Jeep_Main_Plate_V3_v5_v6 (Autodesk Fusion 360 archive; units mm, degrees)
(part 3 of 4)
sketch "Sketch11" plane through (0, 0, 2) normal (0, 0, 1) x axis (-1, 0, 0)
  line L1 (0.6323, -2.2) -> (-11.4211, -2.2)
  line L2 (17.4051, 39.633) -> (0.6323, -2.2)
  line L3 (7.0123, 43.8) -> (17.4051, 39.633)
  line L4 (3.9887, 36.2589) -> (7.0123, 43.8)
  line L5 (2.418, 37.7236) -> (3.9887, 36.2589)
  line L6 (-10.5895, 5.2816) -> (2.418, 37.7236)
  line L7 (-8.4377, 5.259) -> (-10.5895, 5.2816)
  line L8 (-11.4211, -2.2) -> (-8.4377, 5.259)
  line L9 (11.4644, 39.8602) -> (12.2087, 41.7165)
  line L10 (4.9672, 42.4652) -> (11.4644, 39.8602)
  line L11 (19.452, 36.6576) -> (10.1703, 40.379)
  line L12 (14.2412, 37.1163) -> (16.0976, 36.372)
  line L13 (14.8112, 38.5183) -> (14.2412, 37.1163)
  line L14 (-4.3662, -9.2924) -> (14.2412, 37.1163)
  point P10 (12.2087, 41.7165)
  point P13 (10.1703, 40.379)
  point P15 (16.0976, 36.372)
  point P17 (14.8112, 38.5183)
  point P11 (11.4644, 39.8602)
  point P12 (4.9672, 42.4652)
  point P14 (19.452, 36.6576)
  point P16 (14.2412, 37.1163)
  point P18 (-4.3662, -9.2924)
  midpoint L3 P10
  coincident L10 P13
  coincident L2 P15
  midpoint L11 P17
  dimension "d95" distance P10 P11 = 2
  dimension "d96" distance P11 P12 = 7
  dimension "d97" distance P13 P14 = 10
  dimension "d98" distance P15 P16 = 2
  dimension "d99" distance P16 P18 = 50
extrude "Extrude11" add sketch "Sketch11" profile of L2 L3 L4 L9 L10 L11 along normal blind 13
sketch "Sketch12" plane through (0, 0, 2) normal (0, 0, 1) x axis (-1, 0, 0)
  line L1 (6.268, 41.9437) -> (16.6608, 37.7767)
  line L2 (3.9887, 36.2589) -> (6.268, 41.9437)
  line L3 (2.418, 37.7236) -> (3.9887, 36.2589)
  line L4 (-10.5895, 5.2816) -> (2.418, 37.7236)
  line L5 (-8.4377, 5.259) -> (-10.5895, 5.2816)
  line L6 (-11.4211, -2.2) -> (-8.4377, 5.259)
  line L7 (0.6323, -2.2) -> (-11.4211, -2.2)
  line L8 (16.6608, 37.7767) -> (0.6323, -2.2)
  line L9 (14.8044, 38.521) -> (16.6608, 37.7767)
  line L10 (-0.0815, 1.3941) -> (14.8044, 38.521)
  line L11 (4, 1.3941) -> (-0.0815, 1.3941)
  point P2 (16.6608, 37.7767)
  point P10 (16.6608, 37.7767)
  point P11 (14.8044, 38.521)
  point P12 (-0.0815, 1.3941)
  point P13 (4, 1.3941)
  coincident P2 P10
  horizontal L11
  dimension "d102" distance P10 P11 = 2
  dimension "d103" distance P11 P12 = 40
  dimension "d104" distance P12 P13 = 4.0815
extrude "Extrude12" add of existing geometry blind 2
sketch "Sketch13" plane through (0, 0, 2) normal (0, 0, 1) x axis (-1, 0, 0)
  line L1 (6.268, 41.9437) -> (18.5171, 37.0324)
  line L2 (3.9887, 36.2589) -> (6.268, 41.9437)
  line L3 (2.418, 37.7236) -> (3.9887, 36.2589)
  line L4 (-10.5895, 5.2816) -> (2.418, 37.7236)
  line L5 (-8.4377, 5.259) -> (-10.5895, 5.2816)
  line L6 (-11.4211, -2.2) -> (-8.4377, 5.259)
  line L7 (0.6323, -2.2) -> (-11.4211, -2.2)
  line L8 (2.4886, -2.9443) -> (0.6323, -2.2)
  line L9 (18.5171, 37.0324) -> (2.4886, -2.9443)
  line L10 (16.6608, 37.7767) -> (18.5171, 37.0324)
  line L11 (1.7749, 0.6498) -> (16.6608, 37.7767)
  line L12 (7.7749, 0.6498) -> (1.7749, 0.6498)
  point P2 (18.5171, 37.0324)
  point P11 (18.5171, 37.0324)
  point P12 (16.6608, 37.7767)
  point P13 (1.7749, 0.6498)
  point P14 (7.7749, 0.6498)
  coincident P2 P11
  dimension "d107" distance P11 P12 = 2
  dimension "d108" distance P12 P13 = 40
  dimension "d109" distance P13 P14 = 6
extrude "Extrude13" add sketch "Sketch13" profile of L1 L9 L10 L11 L12 along normal blind 10
sketch "Sketch14" plane through (-3.161, 1.2674, 0) normal (-0.9282, 0.3721, 0) x axis (-0.3721, -0.9282, 0)
  line L1 (43.2636, 15) -> (43.2636, 0)
  line L2 (41.2636, 15) -> (43.2636, 15)
  line L3 (41.2636, 12) -> (41.2636, 15)
  line L4 (2.0655, 12) -> (41.2636, 12)
  line L5 (2.0655, 2) -> (2.0655, 12)
  line L6 (-1.8067, 2) -> (2.0655, 2)
  line L7 (-1.8067, 0) -> (-1.8067, 2)
  line L8 (43.2636, 0) -> (-1.8067, 0)
sketch "Sketch15" plane through (0, 0, 2) normal (0, 0, 1) x axis (-1, 0, 0)
  line L1 (1.7749, 0.6498) -> (3.9296, 0.6498)
  line L2 (16.6608, 37.7767) -> (1.7749, 0.6498)
  line L3 (6.268, 41.9437) -> (16.6608, 37.7767)
  line L4 (3.9887, 36.2589) -> (6.268, 41.9437)
  line L5 (2.418, 37.7236) -> (3.9887, 36.2589)
  line L6 (-10.5895, 5.2816) -> (2.418, 37.7236)
  line L7 (-8.4377, 5.259) -> (-10.5895, 5.2816)
  line L8 (-11.4211, -2.2) -> (-8.4377, 5.259)
  line L9 (0.6323, -2.2) -> (-11.4211, -2.2)
  line L10 (2.4886, -2.9443) -> (0.6323, -2.2)
  line L11 (3.9296, 0.6498) -> (2.4886, -2.9443)
  arc A1 centre (-11.4211, 40.5698) radius 42.7698 clockwise from (3.9296, 0.6498) to (-11.4211, -2.2)
  point P10 (-11.4211, -2.2)
  point P14 (-11.4211, -2.2)
  point P2 (3.9296, 0.6498)
  point P13 (3.9296, 0.6498)
  tangent L9 A1
  coincident P10 P14
  coincident P2 P13
extrude "Extrude14" cut sketch "Sketch15" profile of L9 L10 L11 A1 against normal blind 4
extrude "Extrude15" add of existing geometry blind 0.5
sketch "Sketch16" plane through (0, 0, 15) normal (0, 0, 1) x axis (-1, 0, 0)
  line L1 (-8.4377, 5.259) -> (-11.4211, -2.2)
  line L2 (-10.5895, 5.2816) -> (-8.4377, 5.259)
  line L3 (2.418, 37.7236) -> (-10.5895, 5.2816)
  line L4 (3.9887, 36.2589) -> (2.418, 37.7236)
  line L5 (6.268, 41.9437) -> (3.9887, 36.2589)
  line L6 (18.9812, 36.8463) -> (6.268, 41.9437)
  line L7 (19.7255, 38.7027) -> (18.9812, 36.8463)
  line L8 (7.0123, 43.8) -> (19.7255, 38.7027)
  line L9 (-5, 43.8) -> (7.0123, 43.8)
  line L10 (-5, 42.6) -> (-5, 43.8)
  line L11 (0, 42.6) -> (-5, 42.6)
  line L12 (-57.3, 0) -> (-43.8, 0)
  line L13 (-60.8, 11) -> (-60.8, 3.5)
  line L14 (-62, 11) -> (-60.8, 11)
  line L15 (-62, 0.8) -> (-62, 11)
  line L16 (-11.4211, -2.2) -> (-59, -2.2)
  arc A1 centre (-49.0833, 49.2491) radius 49.5316 clockwise from (0, 42.6) to (-43.8, 0)
  arc A2 centre (-54.6577, 6.1423) radius 6.6865 clockwise from (-57.3, 0) to (-60.8, 3.5)
  arc A3 centre (-59, 0.8) radius 3 clockwise from (-59, -2.2) to (-62, 0.8)
extrude "Extrude16" cut of existing geometry blind -0.9
sketch "Sketch17" plane through (0, 0, 15) normal (0, 0, 1) x axis (-1, 0, 0)
  line L1 (-8.4377, 5.259) -> (-11.4211, -2.2)
  line L2 (-10.5895, 5.2816) -> (-8.4377, 5.259)
  line L3 (2.418, 37.7236) -> (-10.5895, 5.2816)
  line L4 (3.9887, 36.2589) -> (2.418, 37.7236)
  line L5 (6.268, 41.9437) -> (3.9887, 36.2589)
  line L6 (18.9812, 36.8463) -> (6.268, 41.9437)
  line L7 (19.7255, 38.7027) -> (18.9812, 36.8463)
  line L8 (7.0123, 43.8) -> (19.7255, 38.7027)
  line L9 (-5, 43.8) -> (7.0123, 43.8)
  line L10 (-5, 42.6) -> (-5, 43.8)
  line L11 (0, 42.6) -> (-5, 42.6)
  line L12 (-57.3, 0) -> (-43.8, 0)
  line L13 (-60.8, 11) -> (-60.8, 3.5)
  line L14 (-62, 11) -> (-60.8, 11)
  line L15 (-62, 0.8) -> (-62, 11)
  line L16 (-11.4211, -2.2) -> (-59, -2.2)
  arc A1 centre (-49.0833, 49.2491) radius 49.5316 clockwise from (0, 42.6) to (-43.8, 0)
  arc A2 centre (-54.6577, 6.1423) radius 6.6865 clockwise from (-57.3, 0) to (-60.8, 3.5)
  arc A3 centre (-59, 0.8) radius 3 clockwise from (-59, -2.2) to (-62, 0.8)
sketch "Sketch18" plane through (0, 0, 12) normal (0, 0, 1) x axis (-1, 0, 0)
  line L1 (2.7445, 0.6498) -> (17.4961, 37.4418)
  line L2 (3.9296, 0.6498) -> (2.7445, 0.6498)
  line L3 (4.3937, 0.4637) -> (3.9296, 0.6498)
  line L4 (18.9812, 36.8463) -> (4.3937, 0.4637)
  line L5 (17.4961, 37.4418) -> (18.9812, 36.8463)
  line L6 (10.0532, 18.8783) -> (17.4961, 37.4418)
  line L7 (15.3685, 18.8783) -> (10.0532, 18.8783)
  point P2 (17.4961, 37.4418)
  point P7 (17.4961, 37.4418)
  point P8 (10.0532, 18.8783)
  coincident P2 P7
  horizontal L7
  dimension "d118" distance P7 P8 = 20
extrude "Extrude17" cut sketch "Sketch18" profile of L1 L2 L3 L4 L7 against normal blind 10
sketch "Sketch19" plane through (0, 0, 2) normal (0, 0, 1) x axis (-1, 0, 0)
  line L1 (6.268, 41.9437) -> (17.4961, 37.4418)
  line L2 (3.9887, 36.2589) -> (6.268, 41.9437)
  line L3 (2.418, 37.7236) -> (3.9887, 36.2589)
  line L4 (-10.5895, 5.2816) -> (2.418, 37.7236)
  line L5 (-8.4377, 5.259) -> (-10.5895, 5.2816)
  line L6 (-11.4211, -2.2) -> (-8.4377, 5.259)
  line L7 (4.3937, 0.4637) -> (3.9296, 0.6498)
  line L8 (11.777, 18.8783) -> (4.3937, 0.4637)
  line L9 (10.0532, 18.8783) -> (11.777, 18.8783)
  line L10 (17.4961, 37.4418) -> (10.0532, 18.8783)
  arc A1 centre (-11.4211, 40.5698) radius 42.7698 clockwise from (3.9296, 0.6498) to (-11.4211, -2.2)
  arc A2 centre (-10.5418, 20.0938) radius 22.3111 clockwise from (6.4823, 5.6727) to (-11.4211, -2.2)
  point P15 (6.4823, 5.6727)
  point P8 (-11.4211, -2.2)
  point P14 (-11.4211, -2.2)
  coincident L8 P15
  coincident P8 P14
extrude "Extrude18" cut sketch "Sketch19" profile of A1 L7 L8 A2 against normal blind 10
fillet "Fillet3" radius 3
fillet "Fillet4" radius 4
fillet "Fillet5" radius 2
fillet "Fillet6" radius 7.25
sketch "Sketch20" plane through (0, 0, 2) normal (0, 0, 1) x axis (-1, 0, 0)
  line L1 (11.777, 18.8783) -> (6.4823, 5.6727)
  line L2 (10.0532, 18.8783) -> (11.777, 18.8783)
  line L3 (17.4961, 37.4418) -> (10.0532, 18.8783)
  line L4 (6.268, 41.9437) -> (17.4961, 37.4418)
  line L5 (3.9887, 36.2589) -> (6.268, 41.9437)
  line L6 (2.418, 37.7236) -> (3.9887, 36.2589)
  line L7 (-10.5895, 5.2816) -> (2.418, 37.7236)
  line L8 (-8.4377, 5.259) -> (-10.5895, 5.2816)
  line L9 (-10.4154, 0.3145) -> (-8.4377, 5.259)
  line L10 (-11.4211, -2.2) -> (-14.1293, -2.2)
  line L11 (3.9887, 36.2589) -> (-8.4377, 5.259)
  arc A1 centre (-10.5418, 20.0938) radius 22.3111 clockwise from (6.4823, 5.6727) to (-7.7545, -2.0425)
  arc A2 centre (-14.1293, 1.8) radius 4 clockwise from (-10.4154, 0.3145) to (-14.1293, -2.2)
  arc A3 centre (-11.4211, 40.5698) radius 42.7698 clockwise from (-7.7545, -2.0425) to (-11.4211, -2.2)
  point P12 (-8.4377, 5.259)
  point P18 (-8.4377, 5.259)
  point P9 (3.9887, 36.2589)
  point P19 (3.9887, 36.2589)
  coincident P12 P18
  coincident P9 P19
extrude "Extrude19" new body sketch "Sketch20" profile of L6 L7 L8 L11 along normal blind 13
sketch "Sketch21" plane through (0, 0, 15) normal (0, 0, 1) x axis (-1, 0, 0)
  line L1 (3.9887, 36.2589) -> (-8.4377, 5.259)
  line L2 (2.418, 37.7236) -> (3.9887, 36.2589)
  line L3 (-10.5895, 5.2816) -> (2.418, 37.7236)
  line L4 (-8.4377, 5.259) -> (-10.5895, 5.2816)
move "Move2"
sketch "Sketch22" plane through (0, 0, 34) normal (0, 0, 1) x axis (-1, 0, 0)
  line L1 (3.9887, 36.2589) -> (-8.4377, 5.259)
  line L2 (2.418, 37.7236) -> (3.9887, 36.2589)
  line L3 (-10.5895, 5.2816) -> (2.418, 37.7236)
  line L4 (-8.4377, 5.259) -> (-10.5895, 5.2816)
sketch "Sketch23" plane through (0, 0, 34) normal (0, 0, 1) x axis (-1, 0, 0)
  line L1 (3.9887, 36.2589) -> (-8.4377, 5.259)
  line L2 (2.418, 37.7236) -> (3.9887, 36.2589)
  line L3 (-10.5895, 5.2816) -> (2.418, 37.7236)
  line L4 (-8.4377, 5.259) -> (-10.5895, 5.2816)
  line L5 (7.0123, 49.1821) -> (1.6236, 35.7422)
  line L6 (18.9812, 36.8463) -> (6.268, 41.9437)
  line L7 (17.4961, 37.4418) -> (6.268, 41.9437)
  line L8 (4.4089, 42.689) -> (7.6114, 41.405)
  line L9 (6.268, 41.9437) -> (3.9887, 36.2589)
  line L10 (-15.0954, -5.9565) -> (-9.5797, 7.8002)
  line L11 (-12.7752, -5.5616) -> (-7.2156, 8.308)
  line L12 (-6.614, -0.9257) -> (-12.183, 1.3072)
  point P6 (1.6236, 35.7422)
  point P12 (7.6114, 41.405)
  point P13 (4.4089, 42.689)
  point P3 (3.9887, 36.2589)
  point P14 (3.9887, 36.2589)
  point P8 (6.268, 41.9437)
  point P15 (6.268, 41.9437)
  point P16 (-9.5797, 7.8002)
  point P18 (-7.2156, 8.308)
  point P20 (-12.183, 1.3072)
  point P21 (-6.614, -0.9257)
  coincident L3 P6
  parallel L3 L5
  coincident L6 P12
  coincident L5 P13
  perpendicular L5 L8
  coincident P3 P14
  coincident P8 P15
  coincident L3 P16
  parallel L3 L10
  coincident L1 P18
  parallel L1 L11
  coincident L10 P20
  dimension "d129" distance P20 P21 = 6
extrude "Extrude20" add sketch "Sketch23" profile of L1 L2 L3 L4 L5 L8 L9 L10 L11 L12 along normal blind 40
sketch "Sketch24" plane through (0, 0, 74) normal (0, 0, 1) x axis (-1, 0, 0)
  line L1 (-12.183, 1.3072) -> (4.4089, 42.689)
  line L2 (-10.3211, 0.5606) -> (-12.183, 1.3072)
  line L3 (3.9887, 36.2589) -> (-10.3211, 0.5606)
  line L4 (6.268, 41.9437) -> (3.9887, 36.2589)
  line L5 (4.4089, 42.689) -> (6.268, 41.9437)
remove_body "RemoveBody1"
sketch "Sketch25" plane through (0, 0, 2) normal (0, 0, 1) x axis (-1, 0, 0)
  line L1 (11.777, 18.8783) -> (6.4823, 5.6727)
  line L2 (10.0532, 18.8783) -> (11.777, 18.8783)
  line L3 (17.4961, 37.4418) -> (10.0532, 18.8783)
  line L4 (6.268, 41.9437) -> (17.4961, 37.4418)
  line L5 (3.9887, 36.2589) -> (6.268, 41.9437)
  line L6 (2.418, 37.7236) -> (3.9887, 36.2589)
  line L7 (-10.5895, 5.2816) -> (2.418, 37.7236)
  line L8 (-8.4377, 5.259) -> (-10.5895, 5.2816)
  line L9 (-10.4154, 0.3145) -> (-8.4377, 5.259)
  line L10 (-11.4211, -2.2) -> (-14.1293, -2.2)
  line L11 (-8.4377, 5.259) -> (-11.4211, -2.2)
  line L12 (8.3111, 47.134) -> (-9.9294, 1.5295)
  line L13 (3.9887, 36.2589) -> (-10.3211, 0.5606)
  line L14 (3.9887, 36.2589) -> (-8.4377, 5.259)
  line L15 (-11.7486, -3.0312) -> (-6.1781, 10.8961)
  line L16 (-25.6775, -38.0332) -> (7.6802, 45.5567)
  arc A1 centre (-10.5418, 20.0938) radius 22.3111 clockwise from (6.4823, 5.6727) to (-7.7545, -2.0425)
  arc A2 centre (-14.1293, 1.8) radius 4 clockwise from (-10.4154, 0.3145) to (-14.1293, -2.2)
  arc A3 centre (-11.4211, 40.5698) radius 42.7698 clockwise from (-7.7545, -2.0425) to (-11.4211, -2.2)
  point P20 (-9.9294, 1.5295)
  point P26 (-6.1781, 10.8961)
  point P28 (7.6802, 45.5567)
  point P27 (-11.7486, -3.0312)
  point P29 (-25.6775, -38.0332)
  midpoint L11 P20
  coincident L13 P26
  coincident L12 P28
  dimension "d132" distance P26 P27 = 15
  dimension "d133" distance P28 P29 = 90
split "Split1"
move "Move3"
sketch "Sketch26" plane through (0, 0, 0) normal (0, 1, 0) x axis (1, 0, 0)
  line L1 (-8.7, 0) -> (-4.2, 0)
  horizontal L1
sketch "Sketch27" plane through (0, 0, 0) normal (0, 0, 1) x axis (1, 0, 0)
  line L1 (-13.3689, -43.8) -> (-4.6131, -43.8)
  line L2 (-13.3689, -41.9403) -> (-13.3689, -43.8)
  line L3 (-4.6131, -41.9403) -> (-13.3689, -41.9403)
  line L4 (-4.6131, -43.8) -> (-4.6131, -41.9403)
  line L5 (5, -43.8) -> (-7.0123, -43.8)
  line L6 (5, -43.8) -> (-5.613, -43.8)
  point P2 (-4.6131, -43.8)
  horizontal L1
  vertical L2
  horizontal L3
  vertical L4
  coincident P2 L5
move "Move4"
sketch "Sketch28" plane through (0, 0, 2) normal (0, 0, 1) x axis (-1, 0, 0)
  line L1 (3.9749, 36.2718) -> (-11.3778, -2.2)
  line L2 (2.418, 37.7236) -> (3.9749, 36.2718)
  line L3 (-10.5895, 5.2816) -> (2.418, 37.7236)
  line L4 (-8.4377, 5.259) -> (-10.5895, 5.2816)
  line L5 (-10.4154, 0.3145) -> (-8.4377, 5.259)
  line L6 (-11.4211, -2.2) -> (-14.1293, -2.2)
  arc A1 centre (-14.1293, 1.8) radius 4 clockwise from (-10.4154, 0.3145) to (-14.1293, -2.2)
  arc A2 centre (-11.4211, 40.5698) radius 42.7698 clockwise from (-11.3778, -2.2) to (-11.4211, -2.2)
sketch "Sketch29" plane through (0, 0, 0) normal (0, 0, 1) x axis (1, 0, 0)
  line L1 (-17.0909, -43.8) -> (-4.2862, -43.8)
  line L2 (-17.0909, -41.9413) -> (-17.0909, -43.8)
  line L3 (-4.2862, -41.9413) -> (-17.0909, -41.9413)
  line L4 (-4.2862, -43.8) -> (-4.2862, -41.9413)
  line L5 (5, -43.8) -> (-5.613, -43.8)
  line L6 (-5.613, -43.8) -> (5, -43.8)
  line L7 (-17.8562, -43.8) -> (-3.9146, -43.8)
  line L8 (-17.8562, -41.9413) -> (-17.8562, -43.8)
  line L9 (-3.9146, -41.9413) -> (-17.8562, -41.9413)
  line L10 (-3.9146, -43.8) -> (-3.9146, -41.9413)
  point P2 (-4.2862, -43.8)
  point P10 (-3.9146, -43.8)
  horizontal L1
  vertical L2
  horizontal L3
  vertical L4
  coincident P2 L5
  horizontal L7
  vertical L8
  horizontal L9
  vertical L10
  coincident L5 P10
sketch "Sketch30" plane through (0, 0, 0) normal (0, 0, 1) x axis (1, 0, 0)
extrude "Extrude21" add sketch "Sketch29" profile of L1 L2 L3 L4 L5 L6 L7 L9 along normal blind 15
sketch "Sketch31" plane through (0, 0, 0) normal (0, 0, 1) x axis (1, 0, 0)
  line L1 (-2.418, -37.7236) -> (-3.9887, -36.2589)
  line L2 (-3.9887, -36.2589) -> (-2.418, -37.7236)
  line L3 (-14.5557, -26.4051) -> (-3.5854, -36.6351)
  line L4 (-15.267, -41.9413) -> (-10.534, -30.1553)
  line L5 (-6.268, -41.9437) -> (-15.267, -41.9413)
  line L6 (-3.9887, -36.2589) -> (-6.268, -41.9437)
  point P6 (-3.5854, -36.6351)
  point P9 (-10.534, -30.1553)
  point P8 (-15.267, -41.9413)
  point P10 (-15.267, -41.9413)
  point P11 (-6.268, -41.9437)
  point P12 (-6.268, -41.9437)
  point P5 (-3.9887, -36.2589)
  point P13 (-3.9887, -36.2589)
  point P7 (-14.5557, -26.4051)
  coincident L1 P6
  coincident L3 P9
  coincident P8 P10
  coincident P11 P12
  coincident P5 P13
  dimension "d136" distance P6 P7 = 15
extrude "Extrude22" add sketch "Sketch31" profile of L3 L4 L5 L6 along normal blind 15
sketch "Sketch32" plane through (0, 0, 0) normal (0, 0, 1) x axis (1, 0, 0)
  line L1 (10.5895, -5.2816) -> (8.4377, -5.259)
  line L2 (8.4377, -5.259) -> (10.5895, -5.2816)
  line L3 (-4.0781, -5.259) -> (9.8776, -5.2741)
  line L4 (2.3778, 2.2) -> (-0.6003, -5.2628)
  line L5 (59, 2.2) -> (11.4211, 2.2)
  line L6 (14.5973, 2.2) -> (2.3778, 2.2)
  line L7 (10.5895, -5.2816) -> (14.5973, 2.2)
  point P6 (9.8776, -5.2741)
  point P9 (-0.6003, -5.2628)
  point P8 (2.3778, 2.2)
  point P10 (2.3778, 2.2)
  point P13 (14.5973, 2.2)
  point P4 (10.5895, -5.2816)
  point P14 (10.5895, -5.2816)
  coincident L1 P6
  coincident L3 P9
  coincident P8 P10
  coincident L5 P13
  coincident P4 P14
extrude "Extrude23" add sketch "Sketch32" along normal blind 15
sketch "Sketch33" plane through (0, 0, 15) normal (0, 0, 1) x axis (-1, 0, 0)
  line L1 (2.418, 37.7236) -> (-10.5895, 5.2816)
  line L2 (3.9749, 36.2718) -> (2.418, 37.7236)
  line L3 (6.2374, 41.9413) -> (3.9749, 36.2718)
  line L4 (6.267, 41.9413) -> (6.2374, 41.9413)
  line L5 (3.9887, 36.2589) -> (6.267, 41.9413)
  line L6 (10.534, 30.1553) -> (3.9887, 36.2589)
  line L7 (12.9861, 36.2614) -> (10.534, 30.1553)
  line L8 (12.9887, 36.2589) -> (12.9861, 36.2614)
  line L9 (15.267, 41.9413) -> (12.9887, 36.2589)
  line L10 (15.274, 41.9413) -> (15.267, 41.9413)
  line L11 (27.9812, 36.8463) -> (15.274, 41.9413)
  line L12 (17.3111, 43.2793) -> (26.8692, 39.447)
  line L13 (17.0909, 43.8) -> (17.0909, 43.3634)
  line L14 (-5, 43.8) -> (17.0909, 43.8)
  line L15 (-5, 42.6) -> (-5, 43.8)
  line L16 (0, 42.6) -> (-5, 42.6)
  line L17 (-57.3, 0) -> (-43.8, 0)
  line L18 (-60.8, 11) -> (-60.8, 3.5)
  line L19 (-62, 11) -> (-60.8, 11)
  line L20 (-62, 0.8) -> (-62, 11)
  line L21 (-14.1293, -2.2) -> (-59, -2.2)
  line L22 (-2.3778, -2.2) -> (-14.1293, -2.2)
  line L23 (0.6003, 5.2628) -> (-2.3778, -2.2)
  line L24 (-9.8776, 5.2741) -> (0.6003, 5.2628)
  line L25 (-10.5895, 5.2816) -> (-9.8776, 5.2741)
  line L26 (9.0671, 46.5544) -> (18.3592, 42.859)
  arc A1 centre (26.1249, 37.5906) radius 2 clockwise from (26.8692, 39.447) to (27.9812, 36.8463)
  arc A2 centre (14.613, 36.55) radius 7.25 clockwise from (17.0909, 43.3634) to (17.3111, 43.2793)
  arc A3 centre (-49.0833, 49.2491) radius 49.5316 clockwise from (0, 42.6) to (-43.8, 0)
  arc A4 centre (-54.6577, 6.1423) radius 6.6865 clockwise from (-57.3, 0) to (-60.8, 3.5)
  arc A5 centre (-59, 0.8) radius 3 clockwise from (-59, -2.2) to (-62, 0.8)
  point P37 (18.3592, 42.859)
  point P38 (9.0671, 46.5544)
  coincident L12 P37
  dimension "d141" distance P37 P38 = 10
extrude "Extrude24" cut sketch "Sketch33" profile of L13 L14 L26 against normal blind 23.5
sketch "Sketch34" plane through (0, 0, 2) normal (0, 0, 1) x axis (-1, 0, 0)
  line L1 (10.534, 30.1553) -> (12.9861, 36.2614)
  line L2 (0.6003, 5.2628) -> (10.534, 30.1553)
  line L3 (-2.3778, -2.2) -> (0.6003, 5.2628)
  line L4 (20.777, 18.8783) -> (15.4823, 5.6727)
  line L5 (19.0532, 18.8783) -> (20.777, 18.8783)
  line L6 (26.4961, 37.4418) -> (19.0532, 18.8783)
  line L7 (15.274, 41.9413) -> (26.4961, 37.4418)
  line L8 (15.267, 41.9413) -> (15.274, 41.9413)
  line L9 (12.9887, 36.2589) -> (15.267, 41.9413)
  line L10 (12.9861, 36.2614) -> (12.9887, 36.2589)
  arc A1 centre (-2.4211, 40.5698) radius 42.7698 clockwise from (1.2455, -2.0425) to (-2.3778, -2.2)
  arc A2 centre (-1.5418, 20.0938) radius 22.3111 clockwise from (15.4823, 5.6727) to (1.2455, -2.0425)
fillet "Fillet7" radius 1
fillet "Fillet8" radius 8.5
sketch "Sketch35" plane through (0, 0, 0) normal (0, 0, 1) x axis (1, 0, 0)
  line L1 (-0.6003, -5.2628) -> (8.4377, -5.259)
  line L2 (-10.534, -30.1553) -> (-0.6003, -5.2628)
  line L3 (-3.9887, -36.2589) -> (-10.534, -30.1553)
  line L4 (8.4377, -5.259) -> (-3.9887, -36.2589)
  point P2 (8.4377, -5.259)
  point P4 (8.4377, -5.259)
  point P3 (-0.6003, -5.2628)
  point P5 (-0.6003, -5.2628)
  point P6 (-10.534, -30.1553)
  point P7 (-10.534, -30.1553)
  point P8 (-3.9887, -36.2589)
  point P9 (-3.9887, -36.2589)
  coincident P2 P4
  coincident P3 P5
  coincident P6 P7
  coincident P8 P9
extrude "Extrude25" add sketch "Sketch35" along normal blind 2
sketch "Sketch36" plane through (0, 0, 15) normal (0, 0, 1) x axis (-1, 0, 0)
  line L1 (-5, 43.8) -> (14.4017, 43.8)
  line L2 (-5, 42.6) -> (-5, 43.8)
  line L3 (0, 42.6) -> (-5, 42.6)
  line L4 (-57.3, 0) -> (-43.8, 0)
  line L5 (-60.8, 11) -> (-60.8, 3.5)
  line L6 (-62, 11) -> (-60.8, 11)
  line L7 (-62, 0.8) -> (-62, 11)
  line L8 (-14.1293, -2.2) -> (-59, -2.2)
  line L9 (-3.0554, -2.2) -> (-14.1293, -2.2)
  line L10 (0.6003, 5.2628) -> (-2.1266, -1.5706)
  line L11 (-9.8776, 5.2741) -> (0.6003, 5.2628)
  line L12 (-10.5895, 5.2816) -> (-9.8776, 5.2741)
  line L13 (2.418, 37.7236) -> (-10.5895, 5.2816)
  line L14 (3.9749, 36.2718) -> (2.418, 37.7236)
  line L15 (6.2374, 41.9413) -> (3.9749, 36.2718)
  line L16 (6.267, 41.9413) -> (6.2374, 41.9413)
  line L17 (3.9887, 36.2589) -> (6.267, 41.9413)
  line L18 (10.534, 30.1553) -> (3.9887, 36.2589)
  line L19 (12.9861, 36.2614) -> (10.534, 30.1553)
  line L20 (12.9887, 36.2589) -> (12.9861, 36.2614)
  line L21 (15.267, 41.9413) -> (12.9887, 36.2589)
  line L22 (15.274, 41.9413) -> (15.267, 41.9413)
  line L23 (27.9812, 36.8463) -> (15.274, 41.9413)
  line L24 (17.3111, 43.2793) -> (26.8692, 39.447)
  arc A1 centre (14.4017, 35.3) radius 8.5 clockwise from (14.4017, 43.8) to (17.0909, 43.3634)
  arc A2 centre (-49.0833, 49.2491) radius 49.5316 clockwise from (0, 42.6) to (-43.8, 0)
  arc A3 centre (-54.6577, 6.1423) radius 6.6865 clockwise from (-57.3, 0) to (-60.8, 3.5)
  arc A4 centre (-59, 0.8) radius 3 clockwise from (-59, -2.2) to (-62, 0.8)
  arc A5 centre (-3.0554, -1.2) radius 1 clockwise from (-2.1266, -1.5706) to (-3.0554, -2.2)
  arc A6 centre (26.1249, 37.5906) radius 2 clockwise from (26.8692, 39.447) to (27.9812, 36.8463)
  arc A7 centre (14.613, 36.55) radius 7.25 clockwise from (17.0909, 43.3634) to (17.3111, 43.2793)
sketch "Sketch37" plane through (0, 0, 15) normal (0, 0, 1) x axis (-1, 0, 0)
  line L1 (-5, 43.8) -> (14.4017, 43.8)
  line L2 (-5, 42.6) -> (-5, 43.8)
  line L3 (0, 42.6) -> (-5, 42.6)
  line L4 (-57.3, 0) -> (-43.8, 0)
  line L5 (-60.8, 11) -> (-60.8, 3.5)
  line L6 (-62, 11) -> (-60.8, 11)
  line L7 (-62, 0.8) -> (-62, 11)
  line L8 (-14.1293, -2.2) -> (-59, -2.2)
  line L9 (-3.0554, -2.2) -> (-14.1293, -2.2)
  line L10 (0.6003, 5.2628) -> (-2.1266, -1.5706)
  line L11 (-9.8776, 5.2741) -> (0.6003, 5.2628)
  line L12 (-10.5895, 5.2816) -> (-9.8776, 5.2741)
  line L13 (2.418, 37.7236) -> (-10.5895, 5.2816)
  line L14 (3.9749, 36.2718) -> (2.418, 37.7236)
  line L15 (6.2374, 41.9413) -> (3.9749, 36.2718)
  line L16 (6.267, 41.9413) -> (6.2374, 41.9413)
  line L17 (3.9887, 36.2589) -> (6.267, 41.9413)
  line L18 (10.534, 30.1553) -> (3.9887, 36.2589)
  line L19 (12.9861, 36.2614) -> (10.534, 30.1553)
  line L20 (12.9887, 36.2589) -> (12.9861, 36.2614)
  line L21 (15.267, 41.9413) -> (12.9887, 36.2589)
  line L22 (15.274, 41.9413) -> (15.267, 41.9413)
  line L23 (27.9812, 36.8463) -> (15.274, 41.9413)
  line L24 (17.3111, 43.2793) -> (26.8692, 39.447)
  arc A1 centre (14.4017, 35.3) radius 8.5 clockwise from (14.4017, 43.8) to (17.0909, 43.3634)
  arc A2 centre (-49.0833, 49.2491) radius 49.5316 clockwise from (0, 42.6) to (-43.8, 0)
  arc A3 centre (-54.6577, 6.1423) radius 6.6865 clockwise from (-57.3, 0) to (-60.8, 3.5)
  arc A4 centre (-59, 0.8) radius 3 clockwise from (-59, -2.2) to (-62, 0.8)
  arc A5 centre (-3.0554, -1.2) radius 1 clockwise from (-2.1266, -1.5706) to (-3.0554, -2.2)
  arc A6 centre (26.1249, 37.5906) radius 2 clockwise from (26.8692, 39.447) to (27.9812, 36.8463)
  arc A7 centre (14.613, 36.55) radius 7.25 clockwise from (17.0909, 43.3634) to (17.3111, 43.2793)
sketch "Sketch38" plane through (0, 0, 15) normal (0, 0, 1) x axis (-1, 0, 0)
  line L1 (-5, 43.8) -> (14.4017, 43.8)
  line L2 (-5, 42.6) -> (-5, 43.8)
  line L3 (0, 42.6) -> (-5, 42.6)
  line L4 (-57.3, 0) -> (-43.8, 0)
  line L5 (-60.8, 11) -> (-60.8, 3.5)
  line L6 (-62, 11) -> (-60.8, 11)
  line L7 (-62, 0.8) -> (-62, 11)
  line L8 (-14.1293, -2.2) -> (-59, -2.2)
  line L9 (-3.0554, -2.2) -> (-14.1293, -2.2)
  line L10 (0.6003, 5.2628) -> (-2.1266, -1.5706)
  line L11 (-9.8776, 5.2741) -> (0.6003, 5.2628)
  line L12 (-10.5895, 5.2816) -> (-9.8776, 5.2741)
  line L13 (2.418, 37.7236) -> (-10.5895, 5.2816)
  line L14 (3.9749, 36.2718) -> (2.418, 37.7236)
  line L15 (6.2374, 41.9413) -> (3.9749, 36.2718)
  line L16 (6.267, 41.9413) -> (6.2374, 41.9413)
  line L17 (3.9887, 36.2589) -> (6.267, 41.9413)
  line L18 (10.534, 30.1553) -> (3.9887, 36.2589)
  line L19 (12.9861, 36.2614) -> (10.534, 30.1553)
  line L20 (12.9887, 36.2589) -> (12.9861, 36.2614)
  line L21 (15.267, 41.9413) -> (12.9887, 36.2589)
  line L22 (15.274, 41.9413) -> (15.267, 41.9413)
  line L23 (27.9812, 36.8463) -> (15.274, 41.9413)
  line L24 (17.3111, 43.2793) -> (26.8692, 39.447)
  arc A1 centre (14.4017, 35.3) radius 8.5 clockwise from (14.4017, 43.8) to (17.0909, 43.3634)
  arc A2 centre (-49.0833, 49.2491) radius 49.5316 clockwise from (0, 42.6) to (-43.8, 0)
  arc A3 centre (-54.6577, 6.1423) radius 6.6865 clockwise from (-57.3, 0) to (-60.8, 3.5)
  arc A4 centre (-59, 0.8) radius 3 clockwise from (-59, -2.2) to (-62, 0.8)
  arc A5 centre (-3.0554, -1.2) radius 1 clockwise from (-2.1266, -1.5706) to (-3.0554, -2.2)
  arc A6 centre (26.1249, 37.5906) radius 2 clockwise from (26.8692, 39.447) to (27.9812, 36.8463)
  arc A7 centre (14.613, 36.55) radius 7.25 clockwise from (17.0909, 43.3634) to (17.3111, 43.2793)
sketch "Sketch39" plane through (10.9473, -4.3893, 0) normal (-0.9282, 0.3721, 0) x axis (-0.3721, -0.9282, 0)
  line L1 (35.9139, 2) -> (0.9613, 2)
  line L2 (35.9139, 15) -> (35.9139, 2)
  line L3 (0.9613, 15) -> (35.9139, 15)
  line L4 (0.9613, 2) -> (0.9613, 15)
sketch "Sketch40" plane through (0, 0, 15) normal (0, 0, 1) x axis (-1, 0, 0)
  line L1 (-5, 43.8) -> (14.4017, 43.8)
  line L2 (-5, 42.6) -> (-5, 43.8)
  line L3 (0, 42.6) -> (-5, 42.6)
  line L4 (-57.3, 0) -> (-43.8, 0)
  line L5 (-60.8, 11) -> (-60.8, 3.5)
  line L6 (-62, 11) -> (-60.8, 11)
  line L7 (-62, 0.8) -> (-62, 11)
  line L8 (-14.1293, -2.2) -> (-59, -2.2)
  line L9 (-3.0554, -2.2) -> (-14.1293, -2.2)
  line L10 (0.6003, 5.2628) -> (-2.1266, -1.5706)
  line L11 (-9.8776, 5.2741) -> (0.6003, 5.2628)
  line L12 (-10.5895, 5.2816) -> (-9.8776, 5.2741)
  line L13 (2.418, 37.7236) -> (-10.5895, 5.2816)
  line L14 (3.9749, 36.2718) -> (2.418, 37.7236)
  line L15 (6.2374, 41.9413) -> (3.9749, 36.2718)
  line L16 (6.267, 41.9413) -> (6.2374, 41.9413)
  line L17 (3.9887, 36.2589) -> (6.267, 41.9413)
  line L18 (10.534, 30.1553) -> (3.9887, 36.2589)
  line L19 (12.9861, 36.2614) -> (10.534, 30.1553)
  line L20 (12.9887, 36.2589) -> (12.9861, 36.2614)
  line L21 (15.267, 41.9413) -> (12.9887, 36.2589)
  line L22 (15.274, 41.9413) -> (15.267, 41.9413)
  line L23 (27.9812, 36.8463) -> (15.274, 41.9413)
  line L24 (17.3111, 43.2793) -> (26.8692, 39.447)
  arc A1 centre (14.4017, 35.3) radius 8.5 clockwise from (14.4017, 43.8) to (17.0909, 43.3634)
  arc A2 centre (-49.0833, 49.2491) radius 49.5316 clockwise from (0, 42.6) to (-43.8, 0)
  arc A3 centre (-54.6577, 6.1423) radius 6.6865 clockwise from (-57.3, 0) to (-60.8, 3.5)
  arc A4 centre (-59, 0.8) radius 3 clockwise from (-59, -2.2) to (-62, 0.8)
  arc A5 centre (-3.0554, -1.2) radius 1 clockwise from (-2.1266, -1.5706) to (-3.0554, -2.2)
  arc A6 centre (26.1249, 37.5906) radius 2 clockwise from (26.8692, 39.447) to (27.9812, 36.8463)
  arc A7 centre (14.613, 36.55) radius 7.25 clockwise from (17.0909, 43.3634) to (17.3111, 43.2793)
sketch "Sketch41" plane through (0, 0, 15) normal (0, 0, 1) x axis (-1, 0, 0)
  line L1 (-5, 43.8) -> (14.4017, 43.8)
  line L2 (-5, 42.6) -> (-5, 43.8)
  line L3 (0, 42.6) -> (-5, 42.6)
  line L4 (-57.3, 0) -> (-43.8, 0)
  line L5 (-60.8, 11) -> (-60.8, 3.5)
  line L6 (-62, 11) -> (-60.8, 11)
  line L7 (-62, 0.8) -> (-62, 11)
  line L8 (-14.1293, -2.2) -> (-59, -2.2)
  line L9 (-3.0554, -2.2) -> (-14.1293, -2.2)
  line L10 (0.6003, 5.2628) -> (-2.1266, -1.5706)
  line L11 (-9.8776, 5.2741) -> (0.6003, 5.2628)
  line L12 (-10.5895, 5.2816) -> (-9.8776, 5.2741)
  line L13 (2.418, 37.7236) -> (-10.5895, 5.2816)
  line L14 (3.9749, 36.2718) -> (2.418, 37.7236)
  line L15 (6.2374, 41.9413) -> (3.9749, 36.2718)
  line L16 (6.267, 41.9413) -> (6.2374, 41.9413)
  line L17 (3.9887, 36.2589) -> (6.267, 41.9413)
  line L18 (10.534, 30.1553) -> (3.9887, 36.2589)
  line L19 (12.9861, 36.2614) -> (10.534, 30.1553)
  line L20 (12.9887, 36.2589) -> (12.9861, 36.2614)
  line L21 (15.267, 41.9413) -> (12.9887, 36.2589)
  line L22 (15.274, 41.9413) -> (15.267, 41.9413)
  line L23 (27.9812, 36.8463) -> (15.274, 41.9413)
  line L24 (17.3111, 43.2793) -> (26.8692, 39.447)
  arc A1 centre (14.4017, 35.3) radius 8.5 clockwise from (14.4017, 43.8) to (17.0909, 43.3634)
  arc A2 centre (-49.0833, 49.2491) radius 49.5316 clockwise from (0, 42.6) to (-43.8, 0)
  arc A3 centre (-54.6577, 6.1423) radius 6.6865 clockwise from (-57.3, 0) to (-60.8, 3.5)
  arc A4 centre (-59, 0.8) radius 3 clockwise from (-59, -2.2) to (-62, 0.8)
  arc A5 centre (-3.0554, -1.2) radius 1 clockwise from (-2.1266, -1.5706) to (-3.0554, -2.2)
  arc A6 centre (26.1249, 37.5906) radius 2 clockwise from (26.8692, 39.447) to (27.9812, 36.8463)
  arc A7 centre (14.613, 36.55) radius 7.25 clockwise from (17.0909, 43.3634) to (17.3111, 43.2793)
sketch "Sketch42" plane through (0, 0, 15) normal (0, 0, 1) x axis (-1, 0, 0)
  line L1 (-5, 43.8) -> (14.4017, 43.8)
  line L2 (-5, 42.6) -> (-5, 43.8)
  line L3 (0, 42.6) -> (-5, 42.6)
  line L4 (-57.3, 0) -> (-43.8, 0)
  line L5 (-60.8, 11) -> (-60.8, 3.5)
  line L6 (-62, 11) -> (-60.8, 11)
  line L7 (-62, 0.8) -> (-62, 11)
  line L8 (-14.1293, -2.2) -> (-59, -2.2)
  line L9 (-3.0554, -2.2) -> (-14.1293, -2.2)
  line L10 (0.6003, 5.2628) -> (-2.1266, -1.5706)
  line L11 (-9.8776, 5.2741) -> (0.6003, 5.2628)
  line L12 (-10.5895, 5.2816) -> (-9.8776, 5.2741)
  line L13 (2.418, 37.7236) -> (-10.5895, 5.2816)
  line L14 (3.9749, 36.2718) -> (2.418, 37.7236)
  line L15 (6.2374, 41.9413) -> (3.9749, 36.2718)
  line L16 (6.267, 41.9413) -> (6.2374, 41.9413)
  line L17 (3.9887, 36.2589) -> (6.267, 41.9413)
  line L18 (10.534, 30.1553) -> (3.9887, 36.2589)
  line L19 (12.9861, 36.2614) -> (10.534, 30.1553)
  line L20 (12.9887, 36.2589) -> (12.9861, 36.2614)
  line L21 (15.267, 41.9413) -> (12.9887, 36.2589)
  line L22 (15.274, 41.9413) -> (15.267, 41.9413)
  line L23 (27.9812, 36.8463) -> (15.274, 41.9413)
  line L24 (17.3111, 43.2793) -> (26.8692, 39.447)
  arc A1 centre (14.4017, 35.3) radius 8.5 clockwise from (14.4017, 43.8) to (17.0909, 43.3634)
  arc A2 centre (-49.0833, 49.2491) radius 49.5316 clockwise from (0, 42.6) to (-43.8, 0)
  arc A3 centre (-54.6577, 6.1423) radius 6.6865 clockwise from (-57.3, 0) to (-60.8, 3.5)
  arc A4 centre (-59, 0.8) radius 3 clockwise from (-59, -2.2) to (-62, 0.8)
  arc A5 centre (-3.0554, -1.2) radius 1 clockwise from (-2.1266, -1.5706) to (-3.0554, -2.2)
  arc A6 centre (26.1249, 37.5906) radius 2 clockwise from (26.8692, 39.447) to (27.9812, 36.8463)
  arc A7 centre (14.613, 36.55) radius 7.25 clockwise from (17.0909, 43.3634) to (17.3111, 43.2793)
sketch "Sketch43" plane through (0, 0, 15) normal (0, 0, 1) x axis (-1, 0, 0)
  line L1 (-5, 43.8) -> (14.4017, 43.8)
  line L2 (-5, 42.6) -> (-5, 43.8)
  line L3 (0, 42.6) -> (-5, 42.6)
  line L4 (-57.3, 0) -> (-43.8, 0)
  line L5 (-60.8, 11) -> (-60.8, 3.5)
  line L6 (-62, 11) -> (-60.8, 11)
  line L7 (-62, 0.8) -> (-62, 11)
  line L8 (-14.1293, -2.2) -> (-59, -2.2)
  line L9 (-3.0554, -2.2) -> (-14.1293, -2.2)
  line L10 (0.6003, 5.2628) -> (-2.1266, -1.5706)
  line L11 (-9.8776, 5.2741) -> (0.6003, 5.2628)
  line L12 (-10.5895, 5.2816) -> (-9.8776, 5.2741)
  line L13 (2.418, 37.7236) -> (-10.5895, 5.2816)
  line L14 (3.9749, 36.2718) -> (2.418, 37.7236)
  line L15 (6.2374, 41.9413) -> (3.9749, 36.2718)
  line L16 (6.267, 41.9413) -> (6.2374, 41.9413)
  line L17 (3.9887, 36.2589) -> (6.267, 41.9413)
  line L18 (10.534, 30.1553) -> (3.9887, 36.2589)
  line L19 (12.9861, 36.2614) -> (10.534, 30.1553)
  line L20 (12.9887, 36.2589) -> (12.9861, 36.2614)
  line L21 (15.267, 41.9413) -> (12.9887, 36.2589)
  line L22 (15.274, 41.9413) -> (15.267, 41.9413)
  line L23 (27.9812, 36.8463) -> (15.274, 41.9413)
  line L24 (17.3111, 43.2793) -> (26.8692, 39.447)
  line L25 (5.1224, 5.2741) -> (-9.8776, 5.2741)
  line L26 (11.5275, 20.7345) -> (2.418, 37.7236)
  line L27 (21.6953, 37.7236) -> (2.418, 37.7236)
  line L28 (6.7923, 10.9964) -> (-10.5895, 5.2816)
  line L29 (7.7077, 5.2816) -> (-10.5895, 5.2816)
  line L30 (-0.7632, 1.8461) -> (12.4608, 34.9534)
  arc A1 centre (14.4017, 35.3) radius 8.5 clockwise from (14.4017, 43.8) to (17.0909, 43.3634)
  arc A2 centre (-49.0833, 49.2491) radius 49.5316 clockwise from (0, 42.6) to (-43.8, 0)
  arc A3 centre (-54.6577, 6.1423) radius 6.6865 clockwise from (-57.3, 0) to (-60.8, 3.5)
  arc A4 centre (-59, 0.8) radius 3 clockwise from (-59, -2.2) to (-62, 0.8)
  arc A5 centre (-3.0554, -1.2) radius 1 clockwise from (-2.1266, -1.5706) to (-3.0554, -2.2)
  arc A6 centre (26.1249, 37.5906) radius 2 clockwise from (26.8692, 39.447) to (27.9812, 36.8463)
  arc A7 centre (14.613, 36.55) radius 7.25 clockwise from (17.0909, 43.3634) to (17.3111, 43.2793)
  point P23 (-9.8776, 5.2741)
  point P40 (-9.8776, 5.2741)
  point P25 (2.418, 37.7236)
  point P42 (2.418, 37.7236)
  point P24 (-10.5895, 5.2816)
  point P45 (-10.5895, 5.2816)
  point P48 (12.4608, 34.9534)
  point P49 (-0.7632, 1.8461)
  coincident P23 P40
  horizontal L25
  coincident P25 P42
  horizontal L27
  coincident P24 P45
  horizontal L29
  coincident L19 P48
  midpoint L10 P49
  dimension "d150" angle L26 L27 = 61.8
  dimension "d151" angle L28 L29 = 18.2
extrude "Extrude26" add sketch "Sketch43" profile of L10 L11 L12 L14 L15 L16 L17 L18 L19 L26 L28 L30 against normal blind 13.5
sketch "Sketch44" plane through (0, 0, 15) normal (0, 0, 1) x axis (-1, 0, 0)
  line L1 (-5, 43.8) -> (14.4017, 43.8)
  line L2 (-5, 42.6) -> (-5, 43.8)
  line L3 (0, 42.6) -> (-5, 42.6)
  line L4 (-57.3, 0) -> (-43.8, 0)
  line L5 (-60.8, 11) -> (-60.8, 3.5)
  line L6 (-62, 11) -> (-60.8, 11)
  line L7 (-62, 0.8) -> (-62, 11)
  line L8 (-14.1293, -2.2) -> (-59, -2.2)
  line L9 (-3.0554, -2.2) -> (-14.1293, -2.2)
  line L10 (-0.7632, 1.8461) -> (-2.1266, -1.5706)
  line L11 (2.3021, 9.5201) -> (-0.7632, 1.8461)
  line L12 (-10.5895, 5.2816) -> (2.3021, 9.5201)
  line L13 (2.418, 37.7236) -> (-10.5895, 5.2816)
  line L14 (8.8076, 25.8072) -> (2.418, 37.7236)
  line L15 (12.4608, 34.9534) -> (8.8076, 25.8072)
  line L16 (12.9861, 36.2614) -> (12.4608, 34.9534)
  line L17 (12.9887, 36.2589) -> (12.9861, 36.2614)
  line L18 (15.267, 41.9413) -> (12.9887, 36.2589)
  line L19 (15.274, 41.9413) -> (15.267, 41.9413)
  line L20 (27.9812, 36.8463) -> (15.274, 41.9413)
  line L21 (17.3111, 43.2793) -> (26.8692, 39.447)
  line L22 (-1.184, 48.54) -> (18.0582, 40.8249)
  arc A1 centre (14.4017, 35.3) radius 8.5 clockwise from (14.4017, 43.8) to (17.0909, 43.3634)
  arc A2 centre (-49.0833, 49.2491) radius 49.5316 clockwise from (0, 42.6) to (-43.8, 0)
  arc A3 centre (-54.6577, 6.1423) radius 6.6865 clockwise from (-57.3, 0) to (-60.8, 3.5)
  arc A4 centre (-59, 0.8) radius 3 clockwise from (-59, -2.2) to (-62, 0.8)
  arc A5 centre (-3.0554, -1.2) radius 1 clockwise from (-2.1266, -1.5706) to (-3.0554, -2.2)
  arc A6 centre (26.1249, 37.5906) radius 2 clockwise from (26.8692, 39.447) to (27.9812, 36.8463)
  arc A7 centre (14.613, 36.55) radius 7.25 clockwise from (17.0909, 43.3634) to (17.3111, 43.2793)
  point P37 (18.0582, 40.8249)
  coincident L20 P37
  parallel L20 L22
sketch "Sketch45" plane through (-11.3786, 4.5622, 0) normal (-0.9282, 0.3721, 0) x axis (-0.3721, -0.9282, 0)
  line L1 (44.6129, 12) -> (44.6129, 0)
  line L2 (28.4866, 12) -> (44.6129, 12)
  line L3 (25.2544, 2) -> (25.2544, 9)
  line L4 (11.027, 2) -> (25.2544, 2)
  line L5 (11.027, 0) -> (11.027, 2)
  line L6 (44.6129, 0) -> (11.027, 0)
  closed curve K1 centre (28.4866, 9)
sketch "Sketch46" plane through (0, 0, 15) normal (0, 0, 1) x axis (-1, 0, 0)
  line L1 (-5, 43.8) -> (14.4017, 43.8)
  line L2 (-5, 42.6) -> (-5, 43.8)
  line L3 (0, 42.6) -> (-5, 42.6)
  line L4 (-57.3, 0) -> (-43.8, 0)
  line L5 (-60.8, 11) -> (-60.8, 3.5)
  line L6 (-62, 11) -> (-60.8, 11)
  line L7 (-62, 0.8) -> (-62, 11)
  line L8 (-14.1293, -2.2) -> (-59, -2.2)
  line L9 (-3.0554, -2.2) -> (-14.1293, -2.2)
  line L10 (-0.7632, 1.8461) -> (-2.1266, -1.5706)
  line L11 (2.3021, 9.5201) -> (-0.7632, 1.8461)
  line L12 (-10.5895, 5.2816) -> (2.3021, 9.5201)
  line L13 (2.418, 37.7236) -> (-10.5895, 5.2816)
  line L14 (8.8076, 25.8072) -> (2.418, 37.7236)
  line L15 (12.4608, 34.9534) -> (8.8076, 25.8072)
  line L16 (12.9861, 36.2614) -> (12.4608, 34.9534)
  line L17 (12.9887, 36.2589) -> (12.9861, 36.2614)
  line L18 (15.267, 41.9413) -> (12.9887, 36.2589)
  line L19 (15.274, 41.9413) -> (15.267, 41.9413)
  line L20 (27.9812, 36.8463) -> (15.274, 41.9413)
  line L21 (17.3111, 43.2793) -> (26.8692, 39.447)
  line L22 (27.9812, 36.8463) -> (15.4823, 5.6727)
  line L23 (15.267, 41.9413) -> (27.9812, 36.8463)
  line L24 (8.8076, 25.8072) -> (15.267, 41.9413)
  line L25 (2.418, 37.7236) -> (8.8076, 25.8072)
  line L26 (-10.5895, 5.2816) -> (2.418, 37.7236)
  line L27 (2.3021, 9.5201) -> (-10.5895, 5.2816)
  line L28 (-3.0554, -2.2) -> (2.3021, 9.5201)
  arc A1 centre (14.4017, 35.3) radius 8.5 clockwise from (14.4017, 43.8) to (17.0909, 43.3634)
  arc A2 centre (-49.0833, 49.2491) radius 49.5316 clockwise from (0, 42.6) to (-43.8, 0)
  arc A3 centre (-54.6577, 6.1423) radius 6.6865 clockwise from (-57.3, 0) to (-60.8, 3.5)
  arc A4 centre (-59, 0.8) radius 3 clockwise from (-59, -2.2) to (-62, 0.8)
  arc A5 centre (-3.0554, -1.2) radius 1 clockwise from (-2.1266, -1.5706) to (-3.0554, -2.2)
  arc A6 centre (26.1249, 37.5906) radius 2 clockwise from (26.8692, 39.447) to (27.9812, 36.8463)
  arc A7 centre (14.613, 36.55) radius 7.25 clockwise from (17.0909, 43.3634) to (17.3111, 43.2793)
  arc A8 centre (-1.6389, 20.2261) radius 22.4708 clockwise from (15.4823, 5.6727) to (-3.0554, -2.2)
  arc A9 centre (-1.5418, 20.0938) radius 22.3111 clockwise from (15.4823, 5.6727) to (1.2455, -2.0425)
  point P38 (15.4823, 5.6727)
  point P40 (15.4823, 5.6727)
  point P19 (-3.0554, -2.2)
  point P37 (-3.0554, -2.2)
  point P44 (15.4823, 5.6727)
  point P32 (27.9812, 36.8463)
  point P45 (27.9812, 36.8463)
  point P46 (27.9812, 36.8463)
  point P30 (15.267, 41.9413)
  point P47 (15.267, 41.9413)
  point P48 (15.267, 41.9413)
  point P26 (8.8076, 25.8072)
  point P49 (8.8076, 25.8072)
  point P50 (8.8076, 25.8072)
  point P25 (2.418, 37.7236)
  point P51 (2.418, 37.7236)
  point P24 (-10.5895, 5.2816)
  point P52 (-10.5895, 5.2816)
  point P53 (-10.5895, 5.2816)
  point P23 (2.3021, 9.5201)
  point P54 (2.3021, 9.5201)
  point P55 (2.3021, 9.5201)
  coincident P38 P40
  coincident P19 P37
  coincident P40 P44
  coincident P32 P45
  coincident P32 P46
  coincident P30 P47
  coincident P30 P48
  coincident P26 P49
  coincident P26 P50
  coincident P25 P51
  coincident P24 P52
  coincident P24 P53
  coincident P23 P54
  coincident P23 P55
extrude "Extrude27" add sketch "Sketch46" profile of A5 L10 L11 L12 L13 L14 A8 L22 L23 L24 L25 L26 L27 L28 against normal blind 2
sketch "Sketch47" plane through (0, 0, 0) normal (0, 0, -1) x axis (1, 0, 0)
  line L1 (-6.267, 41.9413) -> (-3.9887, 36.2589)
  line L2 (-6.2374, 41.9413) -> (-6.267, 41.9413)
  line L3 (0.251, 25.6822) -> (-6.2374, 41.9413)
  line L4 (-3.9887, 36.2589) -> (0.251, 25.6822)
  line L5 (-26.8692, 39.447) -> (-17.3111, 43.2793)
  line L6 (-15.4823, 5.6727) -> (-27.9812, 36.8463)
  line L7 (11.4211, -2.2) -> (2.3778, -2.2)
  line L8 (59, -2.2) -> (11.4211, -2.2)
  line L9 (62, 11) -> (62, 0.8)
  line L10 (60.8, 11) -> (62, 11)
  line L11 (60.8, 3.5) -> (60.8, 11)
  line L12 (43.8, 0) -> (57.3, 0)
  line L13 (5, 42.6) -> (0, 42.6)
  line L14 (5, 43.8) -> (5, 42.6)
  line L15 (-14.4017, 43.8) -> (5, 43.8)
  line L16 (-0.6003, 5.2628) -> (3.0554, -2.2)
  line L17 (10.5895, 5.2816) -> (-0.6003, 5.2628)
  line L18 (-2.418, 37.7236) -> (10.5895, 5.2816)
  line L19 (-10.534, 30.1553) -> (-2.418, 37.7236)
  line L20 (-15.267, 41.9413) -> (-10.534, 30.1553)
  line L21 (-27.9812, 36.8463) -> (-15.267, 41.9413)
  arc A1 centre (-14.4017, 35.3) radius 8.5 clockwise from (-17.0909, 43.3634) to (-14.4017, 43.8)
  arc A2 centre (-14.613, 36.55) radius 7.25 clockwise from (-17.3111, 43.2793) to (-17.0909, 43.3634)
  arc A3 centre (-26.1249, 37.5906) radius 2 clockwise from (-27.9812, 36.8463) to (-26.8692, 39.447)
  arc A4 centre (1.5418, 20.0938) radius 22.3111 clockwise from (-1.2455, -2.0425) to (-15.4823, 5.6727)
  arc A5 centre (2.4211, 40.5698) radius 42.7698 clockwise from (2.3778, -2.2) to (-1.2455, -2.0425)
  arc A6 centre (59, 0.8) radius 3 clockwise from (62, 0.8) to (59, -2.2)
  arc A7 centre (54.6577, 6.1423) radius 6.6865 clockwise from (60.8, 3.5) to (57.3, 0)
  arc A8 centre (49.0833, 49.2491) radius 49.5316 clockwise from (43.8, 0) to (0, 42.6)
  point P34 (3.0554, -2.2)
  point P36 (3.0554, -2.2)
  point P35 (-0.6003, 5.2628)
  point P37 (-0.6003, 5.2628)
  point P38 (10.5895, 5.2816)
  point P39 (10.5895, 5.2816)
  point P40 (-2.418, 37.7236)
  point P41 (-2.418, 37.7236)
  point P42 (-10.534, 30.1553)
  point P43 (-10.534, 30.1553)
  point P44 (-15.267, 41.9413)
  point P45 (-15.267, 41.9413)
  point P12 (-27.9812, 36.8463)
  point P46 (-27.9812, 36.8463)
  coincident P34 P36
  coincident P35 P37
  coincident P38 P39
  coincident P40 P41
  coincident P42 P43
  coincident P44 P45
  coincident P12 P46
sketch "Sketch48" plane through (0, 0, 0) normal (0, 0, -1) x axis (1, 0, 0)
  line L1 (-6.267, 41.9413) -> (-3.9887, 36.2589)
  line L2 (-6.2374, 41.9413) -> (-6.267, 41.9413)
  line L3 (0.251, 25.6822) -> (-6.2374, 41.9413)
  line L4 (-3.9887, 36.2589) -> (0.251, 25.6822)
  line L5 (-26.8692, 39.447) -> (-17.3111, 43.2793)
  line L6 (-15.4823, 5.6727) -> (-27.9812, 36.8463)
  line L7 (11.4211, -2.2) -> (2.3778, -2.2)
  line L8 (59, -2.2) -> (11.4211, -2.2)
  line L9 (62, 11) -> (62, 0.8)
  line L10 (60.8, 11) -> (62, 11)
  line L11 (60.8, 3.5) -> (60.8, 11)
  line L12 (43.8, 0) -> (57.3, 0)
  line L13 (5, 42.6) -> (0, 42.6)
  line L14 (5, 43.8) -> (5, 42.6)
  line L15 (-14.4017, 43.8) -> (5, 43.8)
  line L16 (-15.267, 41.9413) -> (-27.9812, 36.8463)
  line L17 (-10.534, 30.1553) -> (-15.267, 41.9413)
  line L18 (-8.8076, 25.8072) -> (-10.534, 30.1553)
  line L19 (-2.418, 37.7236) -> (-8.8076, 25.8072)
  line L20 (10.5895, 5.2816) -> (-2.418, 37.7236)
  line L21 (-2.3021, 9.5201) -> (10.5895, 5.2816)
  line L22 (2.2107, -1.7352) -> (-2.3021, 9.5201)
  arc A1 centre (-14.4017, 35.3) radius 8.5 clockwise from (-17.0909, 43.3634) to (-14.4017, 43.8)
  arc A2 centre (-14.613, 36.55) radius 7.25 clockwise from (-17.3111, 43.2793) to (-17.0909, 43.3634)
  arc A3 centre (-26.1249, 37.5906) radius 2 clockwise from (-27.9812, 36.8463) to (-26.8692, 39.447)
  arc A4 centre (1.5418, 20.0938) radius 22.3111 clockwise from (-1.2455, -2.0425) to (-15.4823, 5.6727)
  arc A5 centre (2.4211, 40.5698) radius 42.7698 clockwise from (2.3778, -2.2) to (-1.2455, -2.0425)
  arc A6 centre (59, 0.8) radius 3 clockwise from (62, 0.8) to (59, -2.2)
  arc A7 centre (54.6577, 6.1423) radius 6.6865 clockwise from (60.8, 3.5) to (57.3, 0)
  arc A8 centre (49.0833, 49.2491) radius 49.5316 clockwise from (43.8, 0) to (0, 42.6)
  arc A9 centre (3.0554, -1.2) radius 1 clockwise from (3.0554, -2.2) to (2.1266, -1.5706)
  point P12 (-27.9812, 36.8463)
  point P35 (-27.9812, 36.8463)
  point P34 (-15.267, 41.9413)
  point P36 (-15.267, 41.9413)
  point P37 (-10.534, 30.1553)
  point P38 (-10.534, 30.1553)
  point P39 (-8.8076, 25.8072)
  point P40 (-8.8076, 25.8072)
  point P41 (-2.418, 37.7236)
  point P42 (-2.418, 37.7236)
  point P43 (10.5895, 5.2816)
  point P44 (10.5895, 5.2816)
  point P45 (-2.3021, 9.5201)
  point P46 (-2.3021, 9.5201)
  point P50 (2.2107, -1.7352)
  coincident P12 P35
  coincident P34 P36
  coincident P37 P38
  coincident P39 P40
  coincident P41 P42
  coincident P43 P44
  coincident P45 P46
  coincident A9 P50
  parallel L20 L22
extrude "Extrude28" cut sketch "Sketch48" profile of L3 L4 L6 A4 A5 L7 L16 L17 L18 L19 L20 L21 A9 L22 against normal blind 12.4
sketch "Sketch49" plane through (-16.6026, -41.4085, 0) normal (0.3721, 0.9282, 0) x axis (-0.9282, 0.3721, 0)
  line L1 (-1.4315, 2) -> (-1.4315, 15)
  line L2 (10.6591, 2) -> (-1.4315, 2)
  line L3 (10.6591, 12) -> (10.6591, 2)
  line L4 (12.2591, 12) -> (10.6591, 12)
  line L5 (12.2591, 13) -> (12.2591, 12)
  line L6 (12.2591, 15) -> (12.2591, 13)
  line L7 (-1.4315, 15) -> (12.2591, 15)
  line L8 (10.6591, 0) -> (10.6591, 2)
  line L9 (10.6591, 13) -> (10.6591, 0)
  line L10 (12.2591, 13) -> (10.6591, 13)
  line L11 (12.2591, -0.0011) -> (12.2591, 13)
  line L12 (10.6591, 0) -> (12.2591, -0.0011)
  line L13 (10.6591, 13) -> (10.6591, 0)
  point P4 (10.6591, 2)
  point P9 (10.6591, 2)
  point P7 (12.2591, 13)
  point P12 (12.2591, 13)
  point P13 (12.2591, 13)
  coincident P4 P9
  perpendicular L2 L8
  perpendicular L2 L9
  coincident P7 P12
  coincident P7 P13
  perpendicular L10 L11
  parallel L9 L13
sketch "Sketch50" plane through (-16.594, -41.4095, 0) normal (0.372, 0.9282, 0) x axis (-0.9282, 0.372, 0)
  line L1 (-1.4295, 2) -> (10.6675, 2)
  line L2 (-1.4295, 0) -> (-1.4295, 2)
  line L3 (12.2675, 0) -> (-1.4295, 0)
  line L4 (12.2675, 12) -> (12.2675, 0)
  line L5 (10.6675, 12) -> (12.2675, 12)
  line L6 (10.6675, 2) -> (10.6675, 12)
  line L7 (10.6675, 0) -> (12.2675, 0)
  line L8 (10.6675, 13) -> (10.6675, 0)
  point P5 (12.2675, 0)
  point P9 (12.2675, 0)
  point P8 (10.6675, 0)
  point P10 (10.6675, 0)
  point P12 (10.6675, 0)
  point P11 (10.6675, 13)
  point P13 (10.6675, 13)
  coincident P5 P9
  coincident P8 P10
  coincident P8 P12
  coincident P11 P13
move "Move5"
move "Move6"
sketch "Sketch51" plane through (13.656, -34.0594, 0) normal (0.3721, -0.9282, 0) x axis (0.9282, 0.3721, 0)
  line L1 (-31.1687, 13) -> (-31.1687, 0)
  line L2 (-43.2593, 13) -> (-31.1687, 13)
  line L3 (-43.2593, 3) -> (-43.2593, 13)
  line L4 (-44.8593, 3) -> (-43.2593, 3)
  line L5 (-44.8593, 2) -> (-44.8593, 3)
  line L6 (-44.8593, 0) -> (-44.8593, 2)
  line L7 (-31.1687, 0) -> (-44.8593, 0)
  line L8 (-42.8593, 2) -> (-44.8593, 2)
  line L9 (-42.8593, 15) -> (-42.8593, 2)
  line L10 (-44.8593, 15) -> (-42.8593, 15)
  line L11 (-44.8593, 2) -> (-44.8593, 15)
  line L12 (-43.26, 15) -> (-44.86, 15)
  point P7 (-44.8593, 2)
  point P9 (-44.8593, 2)
  point P11 (-42.8593, 15)
  point P12 (-42.8593, 15)
  point P13 (-44.8593, 15)
  point P14 (-44.8593, 15)
  point P10 (-42.8593, 2)
  point P15 (-44.86, 15)
  point P16 (-43.26, 15)
  coincident P7 P9
  coincident P11 P12
  perpendicular L2 L9
  coincident P13 P14
  perpendicular L8 L11
  dimension "d158" distance P9 P10 = 2
  dimension "d159" distance P15 P16 = 1.6
sketch "Sketch52" plane through (13.6527, -34.0698, 0) normal (0.372, -0.9282, 0) x axis (0.9282, 0.372, 0)
  line L1 (-31.1553, 13) -> (-43.2524, 13)
  line L2 (-31.1553, 15) -> (-31.1553, 13)
  line L3 (-44.8524, 15) -> (-31.1553, 15)
  line L4 (-44.8524, 3) -> (-44.8524, 15)
  line L5 (-43.2524, 3) -> (-44.8524, 3)
  line L6 (-43.2524, 13) -> (-43.2524, 3)
  line L7 (-43.2524, 15) -> (-44.8524, 15)
  line L8 (-42.8524, 2) -> (-44.8524, 2)
  line L9 (-43.2524, 2) -> (-43.2524, 15)
  line L10 (-44.8524, 2) -> (-43.2524, 2)
  line L11 (-44.8524, 15) -> (-44.8524, 2)
  point P5 (-44.8524, 15)
  point P8 (-44.8524, 15)
  point P12 (-43.2524, 2)
  point P10 (-44.8524, 2)
  point P13 (-44.8524, 2)
  point P14 (-44.8524, 15)
  point P9 (-43.2524, 15)
  coincident P5 P8
  coincident L8 P12
  perpendicular L3 L9
  coincident P10 P13
  coincident P5 P14
  dimension "d160" distance P8 P9 = 1.6
extrude "Extrude29" add sketch "Sketch52" profile of L3 L4 L5 L6 L7 L8 L9 L10 L11 along normal blind 15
